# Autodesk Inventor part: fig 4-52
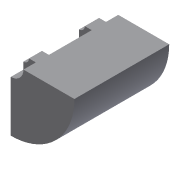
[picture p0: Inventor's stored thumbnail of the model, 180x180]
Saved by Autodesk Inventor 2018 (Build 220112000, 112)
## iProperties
Created: 2010-02
Part Number: fig 4-52
Document SubType Name: Modeling
Designer: CADSoft
Density: 1 g/cm^3
Material: Generic
Appearance: Default
Author: CADSoft
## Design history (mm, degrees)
sketch "Sketch1"
  geometry: L1 (4.005, 30.039)-(20.155, 30.039); L2 (20.155, 30.039)-(20.155, 0); L3 (20.155, 0)-(4.005, 0); L4 (4.005, 26.163)-(1.809, 26.163); L5 (1.809, 26.163)-(1.809, 21.641); L6 (1.809, 21.641)-(4.005, 21.641); L7 (4.005, 3.941)-(1.809, 3.941); L8 (1.809, 3.941)-(1.809, 8.075); L9 (1.809, 8.075)-(4.005, 8.075); L10 (4.005, 26.163)-(4.005, 30.039); L11 (4.005, 0)-(4.005, 3.941); L12 (4.005, 8.075)-(4.005, 21.641); L13 (0, 31.977)-(0, -5.62); 1 further point
  constraints: 26 end point
revolve "Revolution1" sketch "Sketch1" stored, may be unused: angle "d0" = 90 deg
body "Solid1"
